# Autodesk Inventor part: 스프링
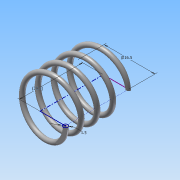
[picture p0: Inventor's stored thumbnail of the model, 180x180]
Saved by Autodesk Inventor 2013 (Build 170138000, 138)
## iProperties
Created: 2015-08
Part Number: 스프링
Material: 강철, 연강
Document SubType Name: Modeling
Designer: Administrator
Mass: 2.84334 g
Surface Area: 9.75661 cm^2
Volume: 0.361748 cm^3
Density: 7.86 g/cm^3
Author: Administrator
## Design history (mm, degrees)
sketch "스케치1"
  geometry: L1 (0, 0)-(8.25, 0); L2 (8.25, 0)-(8.25, 28); L3 (8.25, 28)-(0, 28); L4 (0, 28)-(0, 0); C1 r 0.75 at (8.25, 0)
  constraints: 8 end point, 2 parallel, 1 centre point, 1 coincident, 1 horizontal, 1 perpendicular
  dimensions: "d0" = 28 distance between parallel lines of L1 L3 (derived); "d2" = 16.5 diameter of L2 L4; "d3" = 1.5 diameter of C1
feature "코일1" sketch "스케치1" pitch "d4" = 10; turns "d6" = 4; dims "d5" = 28 (= d0), "d7" = 0, angle "d8" = 90 deg, angle "d9" = 90 deg, "d10" = 0, "d11" = 0
feature "분할1"
node "작업 평면1"
feature "분할2"
node "솔리드1"
other parameters: "d12" = 90 deg
